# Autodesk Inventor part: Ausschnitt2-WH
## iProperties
Created: 2008-06
Part Number: Ausschnitt2-WH
Document SubType Name: Modeling
Designer: WH
Density: 1 g/cm^3
Author: WH
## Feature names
1. Umdrehung1 [Revolution]
2. Extrusion1
